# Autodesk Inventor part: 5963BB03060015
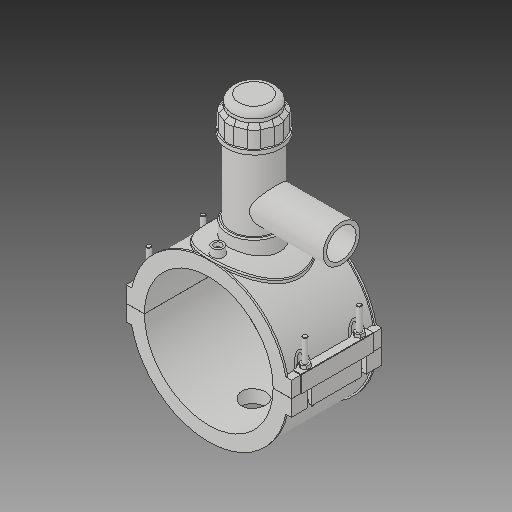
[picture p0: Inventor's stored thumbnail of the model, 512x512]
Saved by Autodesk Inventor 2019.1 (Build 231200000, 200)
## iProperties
Created: 2017-07
Part Number: 5963BB03060015
Material: Generic
Description: PLASSON TAPPING SADDLE 6''IPS x 1 1/2''IPS
Document SubType Name: Modeling
Designer: KIM
Mass: 1712.7 g
Surface Area: 2671.49 cm^2
Volume: 1712.7 cm^3
Density: 1 g/cm^3
Appearance: Default
Author: KIM
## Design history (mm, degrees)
derived "5963B.ipt"
feature "Solid1::5963B.ipt"
feature "Solid2::5963B.ipt"
feature "Solid4::5963B.ipt"
feature "Solid5::5963B.ipt"
tag "TaggingFeature1"
body "Solid1"
body "Solid2"
other parameters: "d0" = 168, "d2" = 215.9, "d3" = 42, "d4" = 118.11, "d5" = 0, "d6" = 0.1, "d8" = 0, "d19" = 6, "d20" = 6, "d21" = 70.866, "d23" = 0, "d24" = 35.433, "d26" = 0, "d29" = 3, "d30" = 56, "d31" = 6, "d32" = 0, "d33" = 0, "d34" = 0.6, "d40" = 104.832, "d41" = 117.6, "d43" = 0, "d45" = 0, "d47" = 171.666, "d70" = 15, "d72" = 0, "d73" = 6, "d75" = 5, "d76" = 0, "d77" = 8.4, "d78" = 114, "d79" = 15, "d80" = 47.244, "d82" = 5 deg, "d84" = 4, "d85" = 14, "d86" = 0, "d87" = 3, "d88" = 0, "d89" = 1, "d90" = 1, "d91" = 94.488, "d92" = 0, "d93" = 0.5, "d94" = 88.42105, "d96" = 205.632, "d97" = 2.3622, "d98" = 0, "d102" = 1.68, "d120" = 140 deg, "d121" = 24.228, "d122" = 20 deg, "d123" = 403.2, "d124" = 120.96, "d126" = 0, "d143" = 173.04, "d145" = 25.84615, "d149" = 2.52, "d150" = 28.43077, "d153" = 118.11, "d154" = 0, "d156" = 100.8, "d157" = 160 deg, "d159" = 6.72, "d161" = 2.52, "d162" = 70.866, "d163" = 0, "d164" = 84, "d167" = 16.8, "d168" = 98.34146, "d170" = 3.2805, "d172" = 0, "d173" = 1, "d175" = 84, "d176" = 20 deg, "d177" = 11.76, "d178" = 33.6, "d180" = 0, "d183" = 13.44, "d184" = 9.408, "d185" = 38.38575, "d186" = 38.38575, "d187" = 100.8, "d188" = 10.08, "d189" = 11.76, "d190" = 0, "d191" = 151.2, "d193" = 6.1236, "d194" = 4.13385, "d195" = 90 deg, "d197" = 0, "d199" = 0, "d200" = 16.8, "d202" = 0, "d203" = 177.038, "d204" = 67.032, "d205" = 49.392, "d206" = 59.976, "d207" = 132.7785, "d208" = 138.08964, "d209" = 164.64534, "d210" = 60.6816, "d211" = 70.56, "d212" = 56.448, "d213" = 36.8766, "d216" = 0, "d217" = 16.8, "d218" = 8.4, "d219" = 1.68, "d222" = 168, "d224" = 0, "d230" = 5.04, "d233" = 6, "d236" = 107.95, "d237" = 35.433, "d238" = 6.02433, "d240" = 35.433, "d241" = 35.433, "d242" = 35.433, "d243" = 6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
